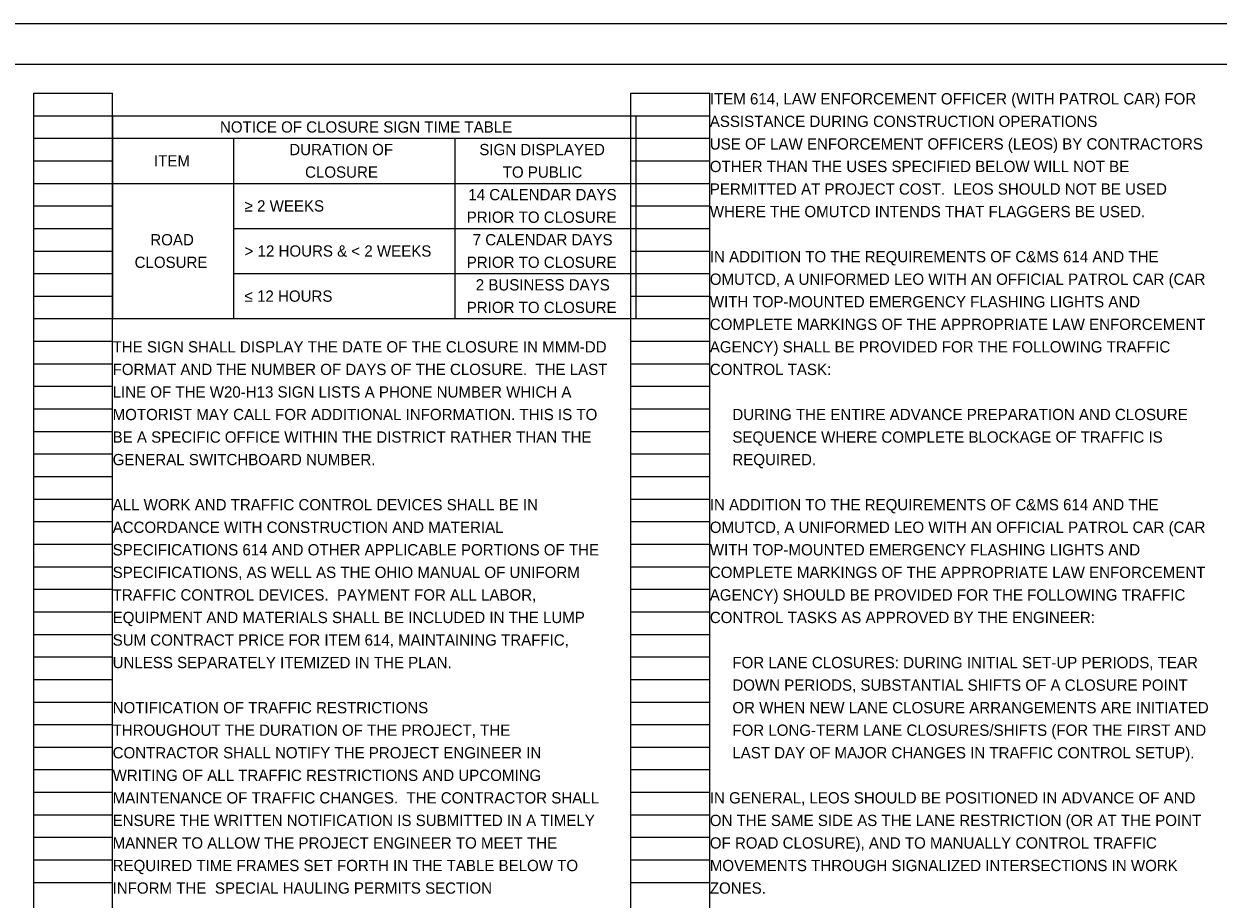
# Model space of a CAD drawing. Extents: x -8.6 to 34, y 0 to 22.
# Drawn here: x 8.72 to 23.56, y 11.13 to 22 of the extents above; entities that cross this region are included whole.
import ezdxf

# ---------------------------------------------------------------- set-up
doc = ezdxf.new("R2010")
doc.units = 0
for name, color, linetype in [('SC_Scratch1', 7, 'Continuous'), ('SH_Border', 7, 'Continuous'), ('SH_Cut_Line', 7, 'Continuous'), ('SH_Data', 7, 'Continuous'), ('SH_Text', 7, 'Continuous')]:
    doc.layers.add(name, color=color, linetype=linetype)

msp = doc.modelspace()

# ---------------------------------------------------------------- linework, layer by layer
at = {"layer": 'SC_Scratch1'}
for p, q in [((8.84, 0.98), (8.84, 21.14)), ((8.84, 21.14), (9.82, 21.14)), ((9.82, 0.98), (9.82, 21.14)), ((16.26, 0.98), (16.26, 21.14)), ((16.26, 21.14), (17.24, 21.14)), ((17.24, 0.98), (17.24, 21.14)), ((8.84, 20.86), (9.82, 20.86)), ((16.26, 20.86), (17.24, 20.86)), ((8.84, 20.58), (9.82, 20.58)), ((16.26, 20.58), (17.24, 20.58)), ((8.84, 20.3), (9.82, 20.3)), ((16.26, 20.3), (17.24, 20.3)), ((8.84, 20.02), (9.82, 20.02)), ((16.26, 20.02), (17.24, 20.02)), ((8.84, 19.74), (9.82, 19.74)), ((16.26, 19.74), (17.24, 19.74)), ((8.84, 19.46), (9.82, 19.46)), ((16.26, 19.46), (17.24, 19.46)), ((8.84, 19.18), (9.82, 19.18)), ((16.26, 19.18), (17.24, 19.18)), ((8.84, 18.9), (9.82, 18.9)), ((16.26, 18.9), (17.24, 18.9)), ((8.84, 18.62), (9.82, 18.62)), ((16.26, 18.62), (17.24, 18.62)), ((8.84, 18.34), (9.82, 18.34)), ((16.26, 18.34), (17.24, 18.34)), ((8.84, 18.06), (9.82, 18.06)), ((16.26, 18.06), (17.24, 18.06)), ((8.84, 17.78), (9.82, 17.78)), ((16.26, 17.78), (17.24, 17.78)), ((8.84, 17.5), (9.82, 17.5)), ((16.26, 17.5), (17.24, 17.5)), ((8.84, 17.22), (9.82, 17.22)), ((16.26, 17.22), (17.24, 17.22)), ((8.84, 16.94), (9.82, 16.94)), ((16.26, 16.94), (17.24, 16.94)), ((8.84, 16.66), (9.82, 16.66)), ((16.26, 16.66), (17.24, 16.66)), ((8.84, 16.38), (9.82, 16.38)), ((16.26, 16.38), (17.24, 16.38)), ((8.84, 16.1), (9.82, 16.1)), ((16.26, 16.1), (17.24, 16.1)), ((8.84, 15.82), (9.82, 15.82)), ((16.26, 15.82), (17.24, 15.82)), ((8.84, 15.54), (9.82, 15.54)), ((16.26, 15.54), (17.24, 15.54)), ((8.84, 15.26), (9.82, 15.26)), ((16.26, 15.26), (17.24, 15.26)), ((8.84, 14.98), (9.82, 14.98)), ((16.26, 14.98), (17.24, 14.98)), ((8.84, 14.7), (9.82, 14.7)), ((16.26, 14.7), (17.24, 14.7)), ((8.84, 14.42), (9.82, 14.42)), ((16.26, 14.42), (17.24, 14.42)), ((8.84, 14.14), (9.82, 14.14)), ((16.26, 14.14), (17.24, 14.14)), ((8.84, 13.86), (9.82, 13.86)), ((16.26, 13.86), (17.24, 13.86)), ((8.84, 13.58), (9.82, 13.58)), ((16.26, 13.58), (17.24, 13.58)), ((8.84, 13.3), (9.82, 13.3)), ((16.26, 13.3), (17.24, 13.3)), ((8.84, 13.02), (9.82, 13.02)), ((16.26, 13.02), (17.24, 13.02)), ((8.84, 12.74), (9.82, 12.74)), ((16.26, 12.74), (17.24, 12.74)), ((8.84, 12.46), (9.82, 12.46)), ((16.26, 12.46), (17.24, 12.46)), ((8.84, 12.18), (9.82, 12.18)), ((16.26, 12.18), (17.24, 12.18)), ((8.84, 11.9), (9.82, 11.9)), ((16.26, 11.9), (17.24, 11.9)), ((8.84, 11.62), (9.82, 11.62)), ((16.26, 11.62), (17.24, 11.62)), ((8.84, 11.34), (9.82, 11.34)), ((16.26, 11.34), (17.24, 11.34))]:
    msp.add_line(p, q, dxfattribs=at)
at = {"layer": 'SH_Border'}
msp.add_lwpolyline([(1.5, 21.5), (33.5, 21.5), (33.5, 0.5), (1.5, 0.5)], close=True, dxfattribs=at)
at = {"layer": 'SH_Cut_Line'}
msp.add_lwpolyline([(0, 0), (34, 0), (34, 22), (0, 22)], close=True, dxfattribs=at)
at = {"layer": 'SH_Data'}
for p, q in [((9.82, 20.86), (9.82, 18.34)), ((9.82, 20.86), (16.32, 20.86)), ((16.32, 20.86), (16.32, 18.34)), ((9.82, 20.58), (16.32, 20.58)), ((11.32, 20.58), (11.32, 18.34)), ((14.07, 20.58), (14.07, 18.34)), ((9.82, 20.02), (16.32, 20.02)), ((11.32, 19.46), (16.32, 19.46)), ((11.32, 18.9), (16.32, 18.9)), ((9.82, 18.34), (16.32, 18.34))]:
    msp.add_line(p, q, dxfattribs=at)

# ---------------------------------------------------------------- texts
for s, p in [('NOTICE OF CLOSURE SIGN TIME TABLE', (11.154, 20.65)), ('DURATION OF', (12.015, 20.37)), ('SIGN DISPLAYED', (14.376, 20.37)), ('ITEM', (10.334, 20.23)), ('CLOSURE', (12.211, 20.09)), ('TO PUBLIC', (14.667, 20.09)), ('ROAD', (10.288, 19.25)), ('CLOSURE', (10.093, 18.97))]:
    msp.add_text(s, height=0.14, dxfattribs=at).set_placement(p)
at = {"layer": 'SH_Text'}
for s, p in [('ITEM 614, LAW ENFORCEMENT OFFICER (WITH PATROL CAR) FOR ', (17.24, 21)), ('ASSISTANCE DURING CONSTRUCTION OPERATIONS', (17.24, 20.72)), ('USE OF LAW ENFORCEMENT OFFICERS (LEOS) BY CONTRACTORS ', (17.24, 20.44)), ('OTHER THAN THE USES SPECIFIED BELOW WILL NOT BE ', (17.24, 20.16)), ('14 CALENDAR DAYS', (14.24, 19.81)), ('PERMITTED AT PROJECT COST.  LEOS SHOULD NOT BE USED ', (17.24, 19.88)), ('≥ 2 WEEKS', (11.46, 19.67)), ('WHERE THE OMUTCD INTENDS THAT FLAGGERS BE USED.', (17.24, 19.6)), ('PRIOR TO CLOSURE', (14.22, 19.53)), ('7 CALENDAR DAYS', (14.294, 19.25)), ('> 12 HOURS & < 2 WEEKS', (11.46, 19.11)), ('IN ADDITION TO THE REQUIREMENTS OF C&MS 614 AND THE ', (17.24, 19.04)), ('PRIOR TO CLOSURE', (14.22, 18.97)), ('OMUTCD, A UNIFORMED LEO WITH AN OFFICIAL PATROL CAR (CAR ', (17.24, 18.76)), ('2 BUSINESS DAYS', (14.332, 18.69)), ('≤ 12 HOURS', (11.46, 18.55)), ('PRIOR TO CLOSURE', (14.22, 18.41)), ('WITH TOP-MOUNTED EMERGENCY FLASHING LIGHTS AND ', (17.24, 18.48)), ('COMPLETE MARKINGS OF THE APPROPRIATE LAW ENFORCEMENT ', (17.24, 18.2)), ('THE SIGN SHALL DISPLAY THE DATE OF THE CLOSURE IN MMM-DD ', (9.82, 17.92)), ('AGENCY) SHALL BE PROVIDED FOR THE FOLLOWING TRAFFIC ', (17.24, 17.92)), ('FORMAT AND THE NUMBER OF DAYS OF THE CLOSURE.  THE LAST ', (9.82, 17.64)), ('CONTROL TASK:', (17.24, 17.64)), ('LINE OF THE W20-H13 SIGN LISTS A PHONE NUMBER WHICH A ', (9.82, 17.36)), ('MOTORIST MAY CALL FOR ADDITIONAL INFORMATION. THIS IS TO ', (9.82, 17.08)), ('DURING THE ENTIRE ADVANCE PREPARATION AND CLOSURE ', (17.52, 17.08)), ('BE A SPECIFIC OFFICE WITHIN THE DISTRICT RATHER THAN THE ', (9.82, 16.8)), ('SEQUENCE WHERE COMPLETE BLOCKAGE OF TRAFFIC IS ', (17.52, 16.8)), ('GENERAL SWITCHBOARD NUMBER.', (9.82, 16.52)), ('REQUIRED.', (17.52, 16.52)), ('ALL WORK AND TRAFFIC CONTROL DEVICES SHALL BE IN ', (9.82, 15.96)), ('IN ADDITION TO THE REQUIREMENTS OF C&MS 614 AND THE ', (17.24, 15.96)), ('ACCORDANCE WITH CONSTRUCTION AND MATERIAL ', (9.82, 15.68)), ('OMUTCD, A UNIFORMED LEO WITH AN OFFICIAL PATROL CAR (CAR ', (17.24, 15.68)), ('SPECIFICATIONS 614 AND OTHER APPLICABLE PORTIONS OF THE ', (9.82, 15.4)), ('WITH TOP-MOUNTED EMERGENCY FLASHING LIGHTS AND ', (17.24, 15.4)), ('SPECIFICATIONS, AS WELL AS THE OHIO MANUAL OF UNIFORM ', (9.82, 15.12)), ('COMPLETE MARKINGS OF THE APPROPRIATE LAW ENFORCEMENT ', (17.24, 15.12)), ('AGENCY) SHOULD BE PROVIDED FOR THE FOLLOWING TRAFFIC ', (17.24, 14.84)), ('TRAFFIC CONTROL DEVICES.  PAYMENT FOR ALL LABOR, ', (9.82, 14.84)), ('EQUIPMENT AND MATERIALS SHALL BE INCLUDED IN THE LUMP ', (9.82, 14.56)), ('CONTROL TASKS AS APPROVED BY THE ENGINEER:', (17.24, 14.56)), ('SUM CONTRACT PRICE FOR ITEM 614, MAINTAINING TRAFFIC, ', (9.82, 14.28)), ('UNLESS SEPARATELY ITEMIZED IN THE PLAN.', (9.82, 14)), ('FOR LANE CLOSURES: DURING INITIAL SET-UP PERIODS, TEAR ', (17.52, 14)), ('DOWN PERIODS, SUBSTANTIAL SHIFTS OF A CLOSURE POINT ', (17.52, 13.72)), ('NOTIFICATION OF TRAFFIC RESTRICTIONS', (9.82, 13.44)), ('OR WHEN NEW LANE CLOSURE ARRANGEMENTS ARE INITIATED ', (17.52, 13.44)), ('THROUGHOUT THE DURATION OF THE PROJECT, THE ', (9.82, 13.16)), ('FOR LONG-TERM LANE CLOSURES/SHIFTS (FOR THE FIRST AND ', (17.52, 13.16)), ('CONTRACTOR SHALL NOTIFY THE PROJECT ENGINEER IN ', (9.82, 12.88)), ('LAST DAY OF MAJOR CHANGES IN TRAFFIC CONTROL SETUP).', (17.52, 12.88)), ('WRITING OF ALL TRAFFIC RESTRICTIONS AND UPCOMING ', (9.82, 12.6)), ('MAINTENANCE OF TRAFFIC CHANGES.  THE CONTRACTOR SHALL ', (9.82, 12.32)), ('IN GENERAL, LEOS SHOULD BE POSITIONED IN ADVANCE OF AND ', (17.24, 12.32)), ('ENSURE THE WRITTEN NOTIFICATION IS SUBMITTED IN A TIMELY ', (9.82, 12.04)), ('ON THE SAME SIDE AS THE LANE RESTRICTION (OR AT THE POINT ', (17.24, 12.04)), ('MANNER TO ALLOW THE PROJECT ENGINEER TO MEET THE ', (9.82, 11.76)), ('OF ROAD CLOSURE), AND TO MANUALLY CONTROL TRAFFIC ', (17.24, 11.76)), ('REQUIRED TIME FRAMES SET FORTH IN THE TABLE BELOW TO ', (9.82, 11.48)), ('MOVEMENTS THROUGH SIGNALIZED INTERSECTIONS IN WORK ', (17.24, 11.48)), ('INFORM THE ', (9.82, 11.2)), ('SPECIAL HAULING PERMITS SECTION ', (11.091, 11.2)), ('ZONES.', (17.24, 11.2))]:
    msp.add_text(s, height=0.14, dxfattribs=at).set_placement(p)

doc.saveas('drawing.dxf')
